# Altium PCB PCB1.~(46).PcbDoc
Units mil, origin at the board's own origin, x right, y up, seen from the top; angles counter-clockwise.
Board outline 6000 x 4000 mil, 2 copper layers (Top Layer, Bottom Layer); 37 components, 28 nets, 157 pads, 79 vias.
Unrouted connection lines stored in the file: 48.
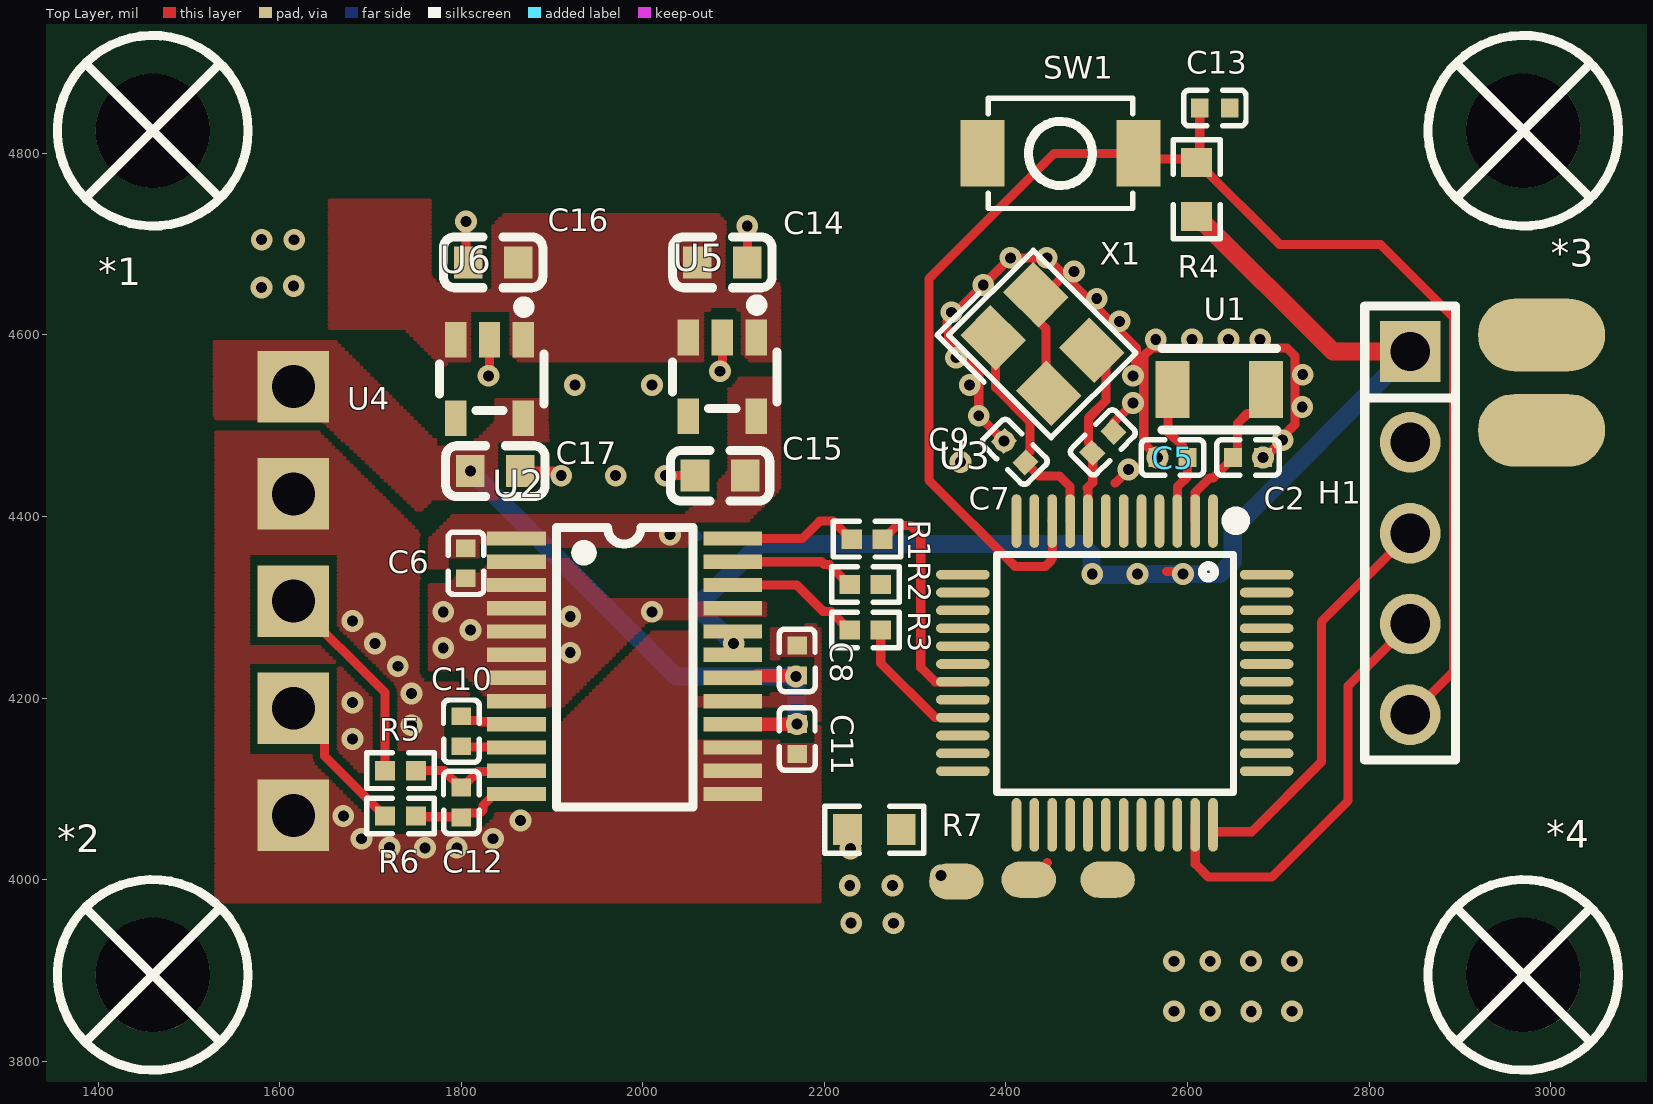
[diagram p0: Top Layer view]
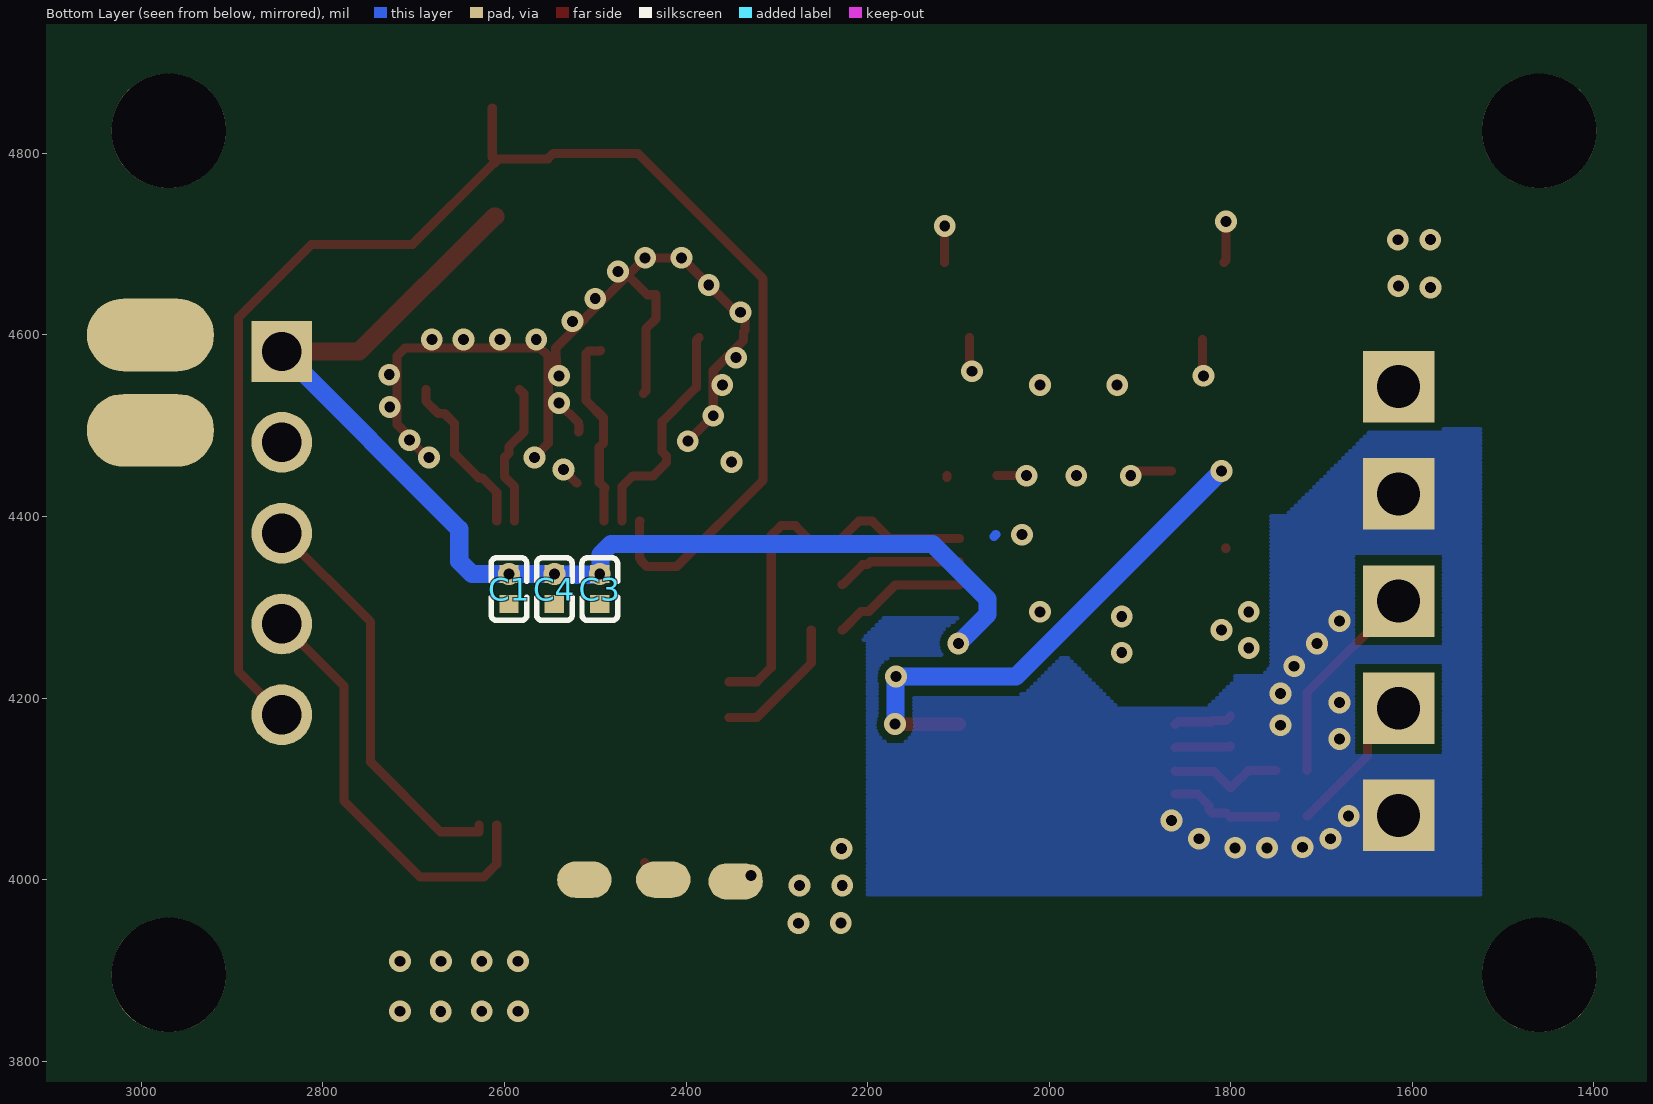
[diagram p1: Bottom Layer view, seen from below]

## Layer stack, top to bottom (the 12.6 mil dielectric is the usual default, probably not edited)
Top Solder: solder mask 0.4, Solder Resist, Dk 3.5
Top Layer: signal copper 1.4
Dielectric 1: dielectric 12.6, FR-4, Dk 4.8
Bottom Layer: signal copper 1.4
Bottom Solder: solder mask 0.4, Solder Resist, Dk 3.5

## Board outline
1000,1000 7000,1000 7000,5000 1000,5000

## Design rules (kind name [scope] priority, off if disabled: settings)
Clearance [All] p1: gap=8 ignorepadtopadclearanceinfootprint=FALSE
ComponentClearance [All] p1: gap=0 collisioncheckmode=3 verticalgap=0 showdistances=FALSE
HoleSize [All] p1: absolutevalues=TRUE maxlimit=130 minlimit=1 maxpercent=80.000 minpercent=20.000
MinimumSolderMaskSliver [All] p1: minsoldermaskwidth=4
PlaneConnect [All] p1: planeconnectstyle=Direct reliefexpansion=20 reliefentries=4 reliefconductorwidth=10 reliefairgap=10
PolygonConnect [All] p1: connectstyle=Direct reliefconductorwidth=10 reliefentries=4 polygonreliefangle="90 Angle" airgapwidth=10
RoutingVias [All] p1: holewidth=28 width=50 viastyle="Through Hole" minholewidth=28 minwidth=50 maxholewidth=28 maxwidth=50
SilkToSilkClearance [All] p1: silktosilkclearance=2
SilkToSolderMaskClearance [IsPad] p1: minsilkscreentomaskgap=2 clearancetoexposedcopper=TRUE
SolderMaskExpansion [All] p1: expansion=0 istentingtop=FALSE
SupplyNets "Schematic Supply Nets_2" [InNet('6V')] p1: voltage=0.000
SupplyNets "Schematic Supply Nets" [InNet('3V3')] p2: voltage=0.000
SupplyNets "Schematic Supply Nets_4" [InNet('5V')] p3: voltage=0.000
SupplyNets "Schematic Supply Nets_3" [InNet('DGND')] p4: voltage=0.000
SupplyNets "Schematic Supply Nets_1" [InNet('AGND')] p5: voltage=0.000
Width [All] p1: maxlimit=50 minlimit=10 preferedwidth=10
24 further rules are at their usual default settings.

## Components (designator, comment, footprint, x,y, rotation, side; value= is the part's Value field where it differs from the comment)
*1 "螺丝孔_1" M3螺丝 1460,4825 r0 top
*2 "螺丝孔_1" M3螺丝 1460,3895 r0 top
*3 "螺丝孔_1" M3螺丝 2970,4825 r0 top
*4 "螺丝孔_1" M3螺丝 2970,3895 r0 top
C1 "cc0402krx7r7bb104" C0402 2595,4320 r270 bottom value=100nF
C2 "cc0402jrnpo9bn220" C0402 2666.54,4465 r180 top value=22pF
C3 "cc0402krx7r7bb104" C0402 2495,4320 r270 bottom value=100nF
C4 "cc0402krx7r7bb104" C0402 2545,4320 r90 bottom value=100nF
C5 "cc0402jrnpo9bn220" C0402 2583.46,4465 r0 top value=22pF
C6 "cc0402krx7r7bb104" C0402 1805,4348.46 r270 top value=100nF
C7 "cc0402jrnpo9bn180" C0402 2506.7,4481.7 r45 top value=18pF
C8 "cc0402krx7r7bb104" C0402 2170,4241.54 r90 top value=100nF
C9 "cc0402jrnpo9bn180" C0402 2409.68,4471.29 r315 top value=18pF
C10 "cc0402krx7r7bb104" C0402 1800,4163.46 r90 top value=100nF
C11 "gcm155r71h103ka55d" C0402 2170,4155 r270 top value=10nF
C12 "gcm155r71h103ka55d" C0402 1800,4085 r270 top value=10nF
C13 "cc0402krx7r7bb104" C0402 2630,4850 r180 top value=100nF
C14 "cga0603x5r105k500jt" C0603 2087.56,4680 r0 top value=1uF
C15 "cga0603x5r105k500jt" C0603 2085,4445 r180 top value=1uF
C16 "cga0603x5r105k500jt" C0603 1835,4680 r180 top value=1uF
C17 "cga0603x5r105k500jt" C0603 1837.44,4450 r0 top value=1uF
H1 "pz254v-11-05p" HDR-TH_5P-P2.54-V-M 2845.25,4381.69 r270 top
R1 "frc0402f47r0ts" R0402 2247.04,4375 r0 top value=47Ω
R2 "frc0402f47r0ts" R0402 2245,4325 r0 top value=47Ω
R3 "frc0402f47r0ts" R0402 2245,4275 r0 top value=47Ω
R4 "frc0603f1002ts" R0603 2610.04,4760.31 r270 top value=10kΩ
R5 "frc0402f1000ts" R0402 1732.96,4120 r0 top value=100Ω
R6 "frc0402f1000ts" R0402 1732.96,4070 r0 top value=100Ω
R7 "0603waf0000t5e" R0603 2255,4055 r0 top value=0Ω
SW1 "ts-1088-ar02016" SW-SMD_L3.9-W3.0-P4.45 2460,4800 r0 top
U1 "fc31m2-32.768-ntlnndtl" CRYSTAL-SMD_L3.2-W1.5 2635,4540 r0 top value=32.768kHz
U2 "ads1232ipwr" TSSOP-24_L7.8-W4.4-P0.65-LS6.4-BL 1980,4235 r270 top
U3 "stm32g031c8t6" LQFP-48_L7.0-W7.0-P0.50-LS9.0-BL 2519.84,4227.68 r180 top
U4 "5个焊盘" 5个焊盘 1615,4543.1 r270 top
U5 "tps7a2033pdbvr" SOT-23-5_L2.9-W1.6-P0.95-LS2.8-BR 2087.56,4553.8 r90 top
U6 "tps7a2050pdbvr" SOT-23-5_L2.9-W1.6-P0.95-LS2.8-BR 1831.01,4551.56 r90 top
X1 "x32258mob4si" CRYSTAL-SMD_4P-L3.2-W2.5-BL 2440,4590 r315 top value=8MHz

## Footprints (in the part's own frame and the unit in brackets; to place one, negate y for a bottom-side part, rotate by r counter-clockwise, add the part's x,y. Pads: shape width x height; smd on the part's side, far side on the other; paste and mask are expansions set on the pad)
5个焊盘 [mm]
  rect 2x2 hole 1.2: 1(0,0) 2(3,0) 3(6.001,0) 4(9,0) 5(12,0)
C0402 [mm]
  rect 0.5x0.54 smd: 1(-0.42,0) 2(0.42,0)
  silkscreen extent -0.87,-0.5 0.87,0.5
C0603 [mm]
  rect 0.8x0.9 smd: 1(-0.7,0) 2(0.7,0)
  silkscreen extent -1.39,-0.71 1.39,0.71
CRYSTAL-SMD_4P-L3.2-W2.5-BL [mm]
  rect 1.4x1.2 smd: 1(-1.1,-0.85) 2(1.1,-0.85) 3(1.1,0.85) 4(-1.1,0.85)
  silkscreen extent -2.26,-1.91 2.03,1.68
CRYSTAL-SMD_L3.2-W1.5 [mm]
  rect 0.95x1.6 smd: 1(-1.308,0) 2(1.308,0)
  silkscreen extent -1.6,-1.14 1.6,1.14
HDR-TH_5P-P2.54-V-M [mm]
  rect 1.7x1.7 hole 1.1: 1(-5.08,0)
  round 1.7 hole 1.1: 2(-2.54,0) 3(0,0) 4(2.54,0) 5(5.08,0)
  silkscreen extent -6.35,-1.27 6.35,1.27
LQFP-48_L7.0-W7.0-P0.50-LS9.0-BL [mm]
  oval 0.27x1.5 smd paste+0 mask+0.05: 1(-2.75,-4.25) 2(-2.25,-4.25) 3(-1.75,-4.25) 4(-1.25,-4.25) 5(-0.75,-4.25) 6(-0.25,-4.25) 7(0.25,-4.25) 8(0.75,-4.25) 9(1.25,-4.25) 10(1.75,-4.25) 11(2.25,-4.25) 12(2.75,-4.25) 25(2.75,4.25) 26(2.25,4.25) 27(1.75,4.25) 28(1.25,4.25) 29(0.75,4.25) 30(0.25,4.25) 31(-0.25,4.25) 32(-0.75,4.25) 33(-1.25,4.25) 34(-1.75,4.25) 35(-2.25,4.25) 36(-2.75,4.25)
  oval 1.5x0.27 smd paste+0 mask+0.05: 13(4.25,-2.75) 14(4.25,-2.25) 15(4.25,-1.75) 16(4.25,-1.25) 17(4.25,-0.75) 18(4.25,-0.25) 19(4.25,0.25) 20(4.25,0.75) 21(4.25,1.25) 22(4.25,1.75) 23(4.25,2.25) 24(4.25,2.75) 37(-4.25,2.75) 38(-4.25,2.25) 39(-4.25,1.75) 40(-4.25,1.25) 41(-4.25,0.75) 42(-4.25,0.25) 43(-4.25,-0.25) 44(-4.25,-0.75) 45(-4.25,-1.25) 46(-4.25,-1.75) 47(-4.25,-2.25) 48(-4.25,-2.75)
  silkscreen extent -3.59,-4.46 3.3,3.34
M3螺丝 [mil]
  round 126 hole 126 paste-99999 mask+4: 1(0,0)
  silkscreen extent -105,-105 105,105
R0402 [mm]
  rect 0.566x0.54 smd paste-100 mask+0.051: 1(-0.433,0) 2(0.433,0)
  silkscreen extent -0.94,-0.5 0.94,0.5
R0603 [mil]
  rect 31.75x34.02 smd paste-3937.01 mask+2: 1(-29.66,0) 2(29.66,0)
  silkscreen extent -55,-26 55,26
SOT-23-5_L2.9-W1.6-P0.95-LS2.8-BR [mm]
  rect 1x0.6 smd paste+0 mask+0.05: 1(1.1,-0.95) 2(1.1,0) 3(1.1,0.95) 4(-1.1,0.95) 5(-1.1,-0.95)
  silkscreen extent -0.89,-1.52 2.16,1.4
SW-SMD_L3.9-W3.0-P4.45 [mm]
  rect 1.23x1.86 smd: 1(-2.185,0) 2(2.185,0)
  silkscreen extent -2.03,-1.54 2.03,1.54
TSSOP-24_L7.8-W4.4-P0.65-LS6.4-BL [mm]
  rect 0.4x1.65 smd: 1(-3.575,-3.023) 2(-2.925,-3.023) 3(-2.275,-3.023) 4(-1.625,-3.023) 5(-0.975,-3.023) 6(-0.325,-3.023) 7(0.325,-3.023) 8(0.975,-3.023) 9(1.625,-3.023) 10(2.275,-3.023) 11(2.925,-3.023) 12(3.575,-3.023) 13(3.575,3.023) 14(2.925,3.023) 15(2.275,3.023) 16(1.625,3.023) 17(0.975,3.023) 18(0.325,3.023) 19(-0.325,3.023) 20(-0.975,3.023) 21(-1.625,3.023) 22(-2.275,3.023) 23(-2.925,3.023) 24(-3.575,3.023)
  silkscreen extent -3.89,-1.91 3.94,1.9

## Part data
C1 C3 C4 C6 C8 C10 C13: "容值:100nF;精度:±10%;额定电压:16V;温度系数:X7R;", JLCPCB Part Class="Extended Part", LCSC Part Name="100nF ±10% 16V", Manufacturer=YAGEO(国巨), ManufacturerPart=CC0402KRX7R7BB104, Temperature Coefficient=X7R, Tolerance=±10%, Voltage Rating=16V
C2 C5: "容值:22pF;精度:±5%;额定电压:50V;温度系数:NP0;", JLCPCB Part Class="Extended Part", LCSC Part Name="22pF ±5% 50V", Manufacturer=YAGEO(国巨), ManufacturerPart=CC0402JRNPO9BN220, Temperature Coefficient=NP0, Tolerance=±5%, Voltage Rating=50V
C7 C9: "容值:18pF;精度:±5%;额定电压:50V;温度系数:NP0;", JLCPCB Part Class="Extended Part", LCSC Part Name="18pF ±5% 50V", Manufacturer=YAGEO(国巨), ManufacturerPart=CC0402JRNPO9BN180, Temperature Coefficient=NP0, Tolerance=±5%, Voltage Rating=50V
C11 C12: "容值:10nF;精度:±10%;额定电压:50V;温度系数:X7R;", JLCPCB Part Class="Extended Part", LCSC Part Name="10nF ±10% 50V", Manufacturer=muRata(村田), ManufacturerPart=GCM155R71H103KA55D, Temperature Coefficient=X7R, Tolerance=±10%, Voltage Rating=50V
C14 C15 C16 C17: "容值:1uF;精度:±10%;额定电压:50V;温度系数:X5R;", JLCPCB Part Class="Extended Part", LCSC Part Name="1uF ±10% 50V 停产", Manufacturer=HRE(芯声), ManufacturerPart=CGA0603X5R105K500JT, Temperature Coefficient=X5R, Tolerance=±10%, Voltage Rating=50V
H1: "插针结构:1x5P;间距:2.54mm;行距:-;圆针/方针:方针;安装方式:直插;排数:单排;总PIN位数:5P;额定电流:3A;额定电压:250V;配合针长度:6mm;塑高:2.5mm;端接针长度:3mm;触头材质:黄铜;触头镀层:-;工作温度:-40℃~+105℃;颜色:黑色;", Color=黑色, Current Rating=3A, JLCPCB Part Class="Extended Part", LCSC Part Name="1x5P 间距:2.54mm 方针 直插", Manufacturer=XFCN(兴飞), ManufacturerPart=PZ254V-11-05P, Operating Temperature=-40℃~+105℃, Voltage Rating (Max)=250V
R1 R2 R3: "电阻类型:厚膜电阻;阻值:47Ω;精度:±1%;功率:62.5mW;工作电压:50V;温度系数:±100ppm/℃;", JLCPCB Part Class="Extended Part", LCSC Part Name="47Ω ±1% 62.5mW 厚膜电阻", Manufacturer=FOJAN(富捷), ManufacturerPart=FRC0402F47R0TS, Operating Temperature=-55℃~+155℃, Power(Watts)=62.5mW, Temperature Coefficient=±100ppm/℃, Tolerance=±1%, Voltage-Supply(Max)=50V
R4: "电阻类型:厚膜电阻;阻值:10kΩ;精度:±1%;功率:100mW;工作电压:75V;温度系数:±100ppm/℃;", JLCPCB Part Class="Extended Part", LCSC Part Name="10kΩ ±1% 100mW 厚膜电阻", Manufacturer=FOJAN(富捷), ManufacturerPart=FRC0603F1002TS, Operating Temperature=-55℃~+155℃, Power(Watts)=100mW, Temperature Coefficient=±100ppm/℃, Tolerance=±1%, Voltage-Supply(Max)=75V
R5 R6: "电阻类型:厚膜电阻;阻值:100Ω;精度:±1%;功率:62.5mW;工作电压:50V;温度系数:±100ppm/℃;", JLCPCB Part Class="Extended Part", LCSC Part Name="100Ω ±1% 62.5mW 厚膜电阻", Manufacturer=FOJAN(富捷), ManufacturerPart=FRC0402F1000TS, Operating Temperature=-55℃~+155℃, Power(Watts)=62.5mW, Temperature Coefficient=±100ppm/℃, Tolerance=±1%, Voltage-Supply(Max)=50V
R7: "电阻类型:厚膜电阻;阻值:0Ω;精度:±1%;功率:100mW;工作电压:75V;温度系数:-;", JLCPCB Part Class="Basic Part", LCSC Part Name="0Ω ±1% 100mW 厚膜电阻", Manufacturer=UNI-ROYAL(厚声), ManufacturerPart=0603WAF0000T5E, Operating Temperature=-55℃~+155℃, Power(Watts)=100mW, Temperature Coefficient=-, Tolerance=±1%, Voltage-Supply(Max)=75V
SW1: "电路结构:单刀单掷;按钮形状:圆形按钮;作用力:1.6N;安装方式:立贴;开关长度:3.9mm;开关宽度:3mm;开关高度:2mm;带支架:不带支架;触点电流:50mA;额定电压:12V;带灯:-;工作寿命:10万次;", Actuator/Cap Color=黑色, Contact Current=50mA, IP Rating=-, JLCPCB Part Class="Basic Part", LCSC Part Name="3.9*3*2mm 立贴 轻触开关", Manufacturer=XUNPU(讯普), ManufacturerPart=TS-1088-AR02016, Operating Force=1.6N, Operating Temperature=-30℃~+80℃, Voltage Rating=12V
U1: "晶振类型:贴片晶振;频率:32.768kHz;常温频差:±10ppm;负载电容:12.5pF;频率稳定度:±10ppm;", Equivalent Series Resistance(ESR)=70kΩ, Frequency Stability=±10ppm, JLCPCB Part Class="Extended Part", LCSC Part Name="3215 2P 32.768kHz 12.5pF ±10ppm -40~+85℃(±10ppm)", Load Capacitance=12.5pF, Manufacturer=HCI(杭晶), ManufacturerPart=FC31M2-32.768-NTLNNDTL, Operating Temperature=-40℃~+85℃
U2: "分辨率(位):24;采样率:10Hz;工作电压:2.7V~5.3V;接口类型:SPI;", Clock Frequency=4.9152MHz；200kHz~8MHz, JLCPCB Part Class="Extended Part", LCSC Part Name="用于桥式传感器的24bit 模数转换器", Manufacturer=TI(德州仪器), ManufacturerPart=ADS1232IPWR, Operating Temperature=-40℃~+105℃, Quiescent Current (Iq)=1.3uA, Temperature Sensors=内置, Voltage - Supply=2.7V~5.3V, Voltage Reference=外置, Voltage Reference Drift=-
U3: "CPU内核:ARM Cortex-M0+;CPU最大主频:64MHz;CPU位数:32 Bit;", JLCPCB Part Class="Extended Part", LCSC Part Name="主流Arm Cortex-M0+ MCU，具有64 KB Flash存储器、8 KB RAM、64 MHz CPU、2x USART、定时器、ADC和通信接口，1.7-3.6V", Manufacturer=ST(意法半导体), ManufacturerPart=STM32G031C8T6, Operating Temperature=-40℃~+85℃, Voltage - Supply=1.7V~3.6V
U5: "输出类型:固定;最大输入电压:6V;输出电压:3.3V;输出电流:300mA;输出极性:正极;", Dropout Voltage=140mV@(300mA), JLCPCB Part Class="Extended Part", LCSC Part Name="具有高 PSRR 的 300mA、超低噪声、低 IQ、低压降 (LDO) 线性稳压器", Manufacturer=TI(德州仪器), ManufacturerPart=TPS7A2033PDBVR, Maximum Input Voltage=6V, Operating Temperature=-40℃~+125℃@(Tj), Output Current=300mA, Output Voltage=3.3V, standby current=15uA
U6: "输出极性:正极;工作电压:6V;输出电压:5V;输出电流:300mA;电源纹波抑制比(PSRR):65dB@(100Hz);输出类型:固定;", JLCPCB Part Class="Extended Part", LCSC Part Name="800mV~5.5V 300mA 6V", Manufacturer=TI(德州仪器), ManufacturerPart=TPS7A2050PDBVR, Operating Temperature=-40℃~+125℃@(Tj), Output Current=300mA, Output Voltage=5V, Power Supply Rejection Ratio (PSRR)=65dB@(100Hz), standby current=6.5uA, Voltage - Supply=6V, Voltage Dropout=140mV@(300mA)
X1: "晶振类型:贴片晶振;频率:8MHz;常温频差:±10ppm;负载电容:12pF;频率稳定度:±20ppm;", Equivalent Series Resistance(ESR)=180Ω, Frequency Stability=±20ppm, JLCPCB Part Class="Extended Part", LCSC Part Name="YSX321SL 8MHZ 4P 3225 12PF ±10PPM -40~85℃ (±20PPM)", Load Capacitance=12pF, Manufacturer=YXC(扬兴晶振), ManufacturerPart=X32258MOB4SI, Normal temperature Frequency Tolerance=±10ppm, Operating Temperature=-40℃~+85℃

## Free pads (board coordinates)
  oval 60x40 all layers, no hole: 7(2345.3,3998) 7(2425,4000) 7(2512,3999.83)
  oval 140x80 all layers, no hole: 7(2990,4495) 7(2990,4600)

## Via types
v1: diameter 24, hole 12, Top Layer to Bottom Layer, tented both sides, 79 vias

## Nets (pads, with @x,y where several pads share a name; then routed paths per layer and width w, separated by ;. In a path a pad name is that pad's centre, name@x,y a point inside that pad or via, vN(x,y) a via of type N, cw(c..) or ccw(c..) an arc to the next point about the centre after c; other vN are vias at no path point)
3V3: C1.1 C3.1 C4.2 C6.1 C15.1 H1.1 R4.2 U2.1 U2.19 U2.20 U3.4 U3.5 U3.6 U5.5 | length 1338.4
  Top Layer w10: C6.1 C6.1@1805.79,4365 ; C15.1@2112.56,4443.03 C15.1 ; v1(2495,4336.54) v1@2497.68,4339.22 ; 2576.89,4339.22 2592.32,4339.22 v1(2595,4336.54)
  Top Layer w20: R4.2 2611.17,4730.65 2760.13,4581.69 H1.1
  Bottom Layer w10: v1@2028.6,4378.6 v1(2030,4380) ; 2058.74,4380 2060.53,4378.21
  Bottom Layer w20: v1(2100,4260) 2067.7,4292.3 2067.7,4308.87 2128.71,4369.89 2482.65,4369.89 2494.37,4358.17 2494.37,4336.7 2494.53,4336.54 v1(2495,4336.54) ; C3.1@2495.69,4335.85 C4.2@2544.31,4335.85 ; C4.2@2545.63,4336.49 C1.1@2594.37,4336.49 ; v1(2595,4336.54) 2635.63,4336.54 2649.85,4350.76 2649.85,4386.29 H1.1
  other v1: 2545,4336.54
5V: C8.1 C11.1 C17.1 U2.16 U2.18 U4.1 U6.5 | length 649.2
  Top Layer w10: v1(2168.61,4223.6) C8.1 ; v1(2169.74,4171.28) C11.1
  Top Layer w15: U2.16 2099.26,4171.28 v1(2169.74,4171.28) ; U2.18 2123.61,4222.21 2125.81,4224.42 2167.79,4224.42 v1(2168.61,4223.6)
  Bottom Layer w10: v1(2168.61,4223.6) v1@2169.17,4223.04 ; v1@2169.17,4171.85 v1(2169.74,4171.28)
  Bottom Layer w20: v1(1810,4450) 2036.39,4223.6 v1(2168.61,4223.6) ; v1@2169.17,4171.85 v1@2169.17,4223.04
6V: C14.1 C16.1 pad.7@2990,4600 U5.1 U5.3 U6.1 U6.3
AGND: C8.2 C11.2 R7.1 U2.13 U2.14 U2.15 U2.17 U4.2 U4.5
  other v1: 1760,4035 1795,4035 1720.87,4035.63 1690,4045 1835,4045 1865,4065 1670,4070 1680,4155 1745,4170 1680,4195 1745,4205 1730,4235 1705,4260 1680,4285
AINN1: R6.1 U4.4 | length 160.9
  Top Layer w10: U4.4 1649.37,4154.39 1649.37,4136.04 1715.41,4070 R6.1
AINP1: R5.1 U4.3 | length 228.7
  Top Layer w10: U4.3 1715.92,4205.94 R5.1
DGND: C1.2 C2.1 C3.2 C4.1 C5.1 C6.2 C7.2 C9.1 C13.1 C14.2 C15.2 C16.2 C17.2 H1.2 pad.7@2345.3,3998 pad.7@2990,4495 R7.2 SW1.1 U2.2 U2.3 U2.4 U2.5 U2.6 U2.7 U2.8 U2.21 U3.7 U5.2 U6.2 X1.2 X1.4 | length 1352.5
  Top Layer w10: v1(1805,4725) 1805,4682.44 C16.2 ; v1(1830,4555) 1831.02,4556.02 U6.2 ; C17.2 1901.21,4450 1906.21,4445 v1(1910,4445) ; v1(2025,4445) C15.2 ; v1(2085,4560) 2087.57,4562.56 U5.2 ; v1(2115,4720) 2115.12,4719.88 C14.2 ; v1(2397.98,4482.98) v1(2370,4510.96) 2370,4560.88 2336.52,4594.36 2336.52,4603.48 2335,4605 2335,4615 v1(2405,4685) v1(2445,4685) v1@2464.14,4665.86 ; X1.2 2444.18,4538.5 2444.18,4606.81 2433.04,4617.95 X1.4 2442.57,4644.29 v1@2464.14,4665.86 ; C7.2 2517.83,4493.95 2517.83,4500.8 2518.39,4501.35 2518.39,4503.39 v1(2540,4525) ; v1(2540,4555) 2542.68,4557.68 2542.68,4574.07 2543.48,4574.87 2543.48,4585.64 2512.06,4617.06 2512.06,4617.94 v1@2464.14,4665.86 ; v1(2566.92,4465) 2566.92,4465.79 2551.8,4480.91 2551.8,4576.88 2560.36,4585.44 2709.64,4585.44 2718.2,4576.88 v1@2718.2,4556.26 ; v1(2683.08,4465) 2687.92,4469.84 C2.1@2687.92,4470.63 ; C2.1@2683.08,4465.79 C2.1@2687.92,4470.63 ; v1(2726.38,4520.61) v1@2718.2,4520.61 ; v1(2726.94,4556.26) v1@2718.2,4556.26 ; C2.1@2687.92,4470.63 2691.22,4470.63 v1(2704.71,4484.12) 2704.71,4487.91 2718.2,4501.4 v1@2718.2,4520.61 ; v1@2718.2,4520.61 v1@2718.2,4556.26
  other v1: 2585,3855 2625,3855 2670.24,3854.54 2715,3855 2585,3910 2625,3910 2670,3910 2715,3910 2229.44,3952.22 2276.16,3951.9 2227.87,3993.61 2274.91,3993.61 2328.34,4004.38 2228.81,4034.06 1920,4250 1780,4255 1810,4275 1920,4290 1780,4295 2010,4295 1970,4445 2350,4460 1925,4545 2010,4545 2360,4545 2345,4575 2565,4595 2605,4595 2645,4595 2680,4595 2525,4615 2340,4625 2500,4640 1579.72,4652.35 1615.25,4654.08 2375,4655 2475,4670 1580,4705 1615.83,4704.92
DOUT: R1.2 U3.19 | length 251.1
  Top Layer w10: R1.2 2264.59,4375 2279.58,4390 2295.22,4390 2306.09,4379.12 2306.09,4233.84 2321.97,4217.96 2352.4,4217.96 U3.19
NetC2_2: C2.2 U1.2 U3.2 | length 183.5
  Top Layer w10: U3.2 2608.54,4395.12 2608.54,4426.49 2624.61,4442.56 2628.35,4442.56 2654.84,4469.06 2654.84,4502.3 2666.05,4513.5 2672.8,4513.5 2686.5,4527.21 U1.2
NetC5_2: C5.2 U1.1 U3.3 | length 160.6
  Top Layer w10: U1.1 2578.5,4535 2578.5,4493.5 2595.16,4476.85 2595.16,4469.84 C5.2 2600,4443.85 2588.86,4432.71 2588.86,4395.12 U3.3
NetC7_1: C7.1 U3.8 X1.3 | length 214.9
  Top Layer w10: U3.8 U3.8 2490.35,4402.44 2490.35,4429.95 2489.11,4431.19 2495.56,4437.63 2495.56,4476.29 2490.91,4480.93 2490.91,4508.56 2510.11,4527.75 2510.11,4579.54 2507.33,4582.33 2495,4582.33 X1.3
NetC9_2: C9.2 U3.9 X1.1 | length 254.5
  Top Layer w10: X1.1 2388.5,4594.18 2388.5,4542.39 2426.34,4504.54 2426.34,4471.41 2421.37,4466.44 C9.2 2436.12,4444.85 2458.69,4444.85 2470.67,4432.86 2470.67,4402.44 2470.67,4395.04 U3.9
NetC10_1: C10.1 U2.10 | length 61.6
  Top Layer w10: C10.1 1800.74,4146.18 1860.25,4146.18 U2.10
NetC10_2: C10.2 U2.9 | length 64.7
  Top Layer w10: C10.2 1804.84,4175.16 1819.84,4175.16 1821.11,4173.89 1858.13,4173.89 U2.9
NetC12_1: C12.1 R5.2 U2.11 | length 126.2
  Top Layer w10: R5.2 1780.75,4120 1799.21,4101.54 C12.1 1800.79,4101.54 1818.52,4119.27 1860.43,4119.27 U2.11
NetC12_2: C12.2 R6.2 U2.12 | length 125.3
  Top Layer w10: R6.2 1750.77,4069.23 1799.23,4069.23 C12.2 1804.84,4073.3 1820.44,4073.3 1823.63,4076.5 1823.63,4081.5 1836.39,4094.26 U2.12
NetR1_1: R1.1 U2.24 | length 147.3
  Top Layer w10: U2.24 2175.54,4375.74 2194.8,4395 2209.49,4395 2229.49,4375 R1.1
NetR2_1: R2.1 U2.23 | length 139.4
  Top Layer w10: U2.23 2196.82,4350.15 2199.94,4347.03 2205.42,4347.03 2227.45,4325 R2.1
NetR3_1: R3.1 U2.22 | length 149.5
  Top Layer w10: U2.22 2169.37,4324.56 2198.42,4295.51 2206.94,4295.51 2227.45,4275 R3.1
NRST: C13.2 H1.5 R4.1 SW1.2 U3.10 | length 1671.2
  Top Layer w10: U3.10 2451.06,4394.88 2451.06,4354.31 2451.1,4354.27 2449.62,4352.79 2449.62,4351.29 2443.25,4344.91 2410.11,4344.91 2315,4440.02 2315,4661.81 2453.19,4800 SW1.2 2552.11,4793.91 R4.1@2611.38,4793.91 ; R4.1 2610.25,4789.76 R4.1@2611.38,4789.76 ; C13.2 2613.46,4795.99 R4.1@2611.38,4793.91 ; H1.5 2893.09,4229.53 2893.09,4619.16 2812.43,4699.82 2701.33,4699.82 R4.1@2611.38,4789.76 ; R4.1@2611.38,4789.76 R4.1@2611.38,4793.91
PDWN: R3.2 U3.21 | length 151.8
  Top Layer w10: R3.2 2262.04,4238.52 2321.97,4178.59 2352.4,4178.59 U3.21
SCLK: R2.2 U3.20
SWCLK: H1.3 U3.36 | length 451.4
  Top Layer w10: U3.36 2628.11,4052.84 2628.27,4052.68 2670.54,4052.68 2747.4,4129.53 2747.4,4283.84 H1.3
SWDIO: H1.4 U3.35 | length 475.3
  Top Layer w10: U3.35 2608.54,4060.24 2608.54,4017.32 2623.09,4002.77 2692.63,4002.77 2776.9,4087.04 2776.9,4213.35 H1.4
USART1_RX: pad.7@2512,3999.83 U3.32
USART1_TX: pad.7@2425,4000 U3.29
USART2_RX: U3.14
USART2_TX: U3.13
pads on no net: *1.1 *2.1 *3.1 *4.1 U3.1 U3.11 U3.12 U3.15 U3.16 U3.17 U3.18 U3.22 U3.23 U3.24 U3.25 U3.26 U3.27 U3.28 U3.30 U3.31 U3.33 U3.34 U3.37 U3.38 U3.39 U3.40 U3.41 U3.42 U3.43 U3.44 U3.45 U3.46 U3.47 U3.48 U5.4 U6.4
copper on no net: | length 62.9
  Top Layer w10: 2425,4000 2426.88,4000 2445.47,4018.59 ; 2504.65,4007.18 2512,3999.83 ; 2520.16,4436.85 v1(2535,4451.69) v1@2535,4455

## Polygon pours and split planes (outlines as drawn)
DGND on Top Layer "NONET_L-01_P-001" (hatched Horizontal grid 4 track 5, remove dead copper, pour order 15): 1389.4,3473.32 1389.4,2330.12 3114.4,2330.12 3114.4,3466.93
5V on Top Layer "NONET_L-01_P-001" (hatched Horizontal grid 4 track 5, remove dead copper, pour order 9): 1893.57,4530 1873.57,4530 1838.57,4530 1838.57,4505 1818.57,4485 1768.57,4485 1658.57,4595 1528.57,4595 1528.57,4505 1645,4505 1680,4475 1753.57,4405 1768.57,4420 1838.57,4420 1838.57,4480 1843.57,4485 1848.57,4480 1895,4480
AGND on Top Layer "NONET_L-01_P-001" (hatched Horizontal grid 4 track 5, remove dead copper, pour order 7): 1565,4495 1640,4495 1755,4380 1755,4225 1795,4225 1827.5,4192.5 1907.5,4192.5 1915,4185 2010,4280 2180,4280 2185,4285 2195,4275 2195,3975 2180,3975 2160,3975 1530,3975 1530,4495
DGND on Top Layer "NONET_L-01_P-001" (hatched Horizontal grid 4 track 5, remove dead copper, pour order 5): 1765,4340 1820,4340 1832.5,4352.5 1830,4355 1830,4365 1905,4365 1960,4310 2135,4310 2135,4290 2130,4285 2005,4285 1905,4185 1830,4185 1830,4200 1800,4230 1765,4230
6V on Top Layer "NONET_L-01_P-001" (hatched Horizontal grid 4 track 5, remove dead copper, pour order 3): 1655,4750 1655,4605 1740,4605 1780,4565 1785,4570 1810,4570 1810,4615 1820,4625 1855,4625 1855,4580 1865,4570 2070,4570 2070,4625 2075,4630 2105,4630 2105,4585 2120,4570 2150,4570 2150,4655 2140,4665 2090,4665 2090,4725 2080,4735 1850,4735 1835,4720 1835,4650 1780,4650 1765,4665 1765,4750
3V3 on Top Layer "NONET_L-01_P-001" (hatched Horizontal grid 4 track 5, remove dead copper, pour order 2): 2095,4555 2095,4450 2045,4400 1790,4400 1765,4375 1765,4340 1820,4340 1845,4365 2045,4365 2070,4390 2110,4390 2150,4430 2150,4545 2140,4555
DGND on Bottom Layer "NONET_L-01_P-001" (hatched Horizontal grid 4 track 5, remove dead copper, pour order 16): 3114.4,3473.32 3114.4,2325.12 1389.4,2325.12 1389.4,3466.93
AGND on Bottom Layer "NONET_L-01_P-001" (hatched Horizontal grid 4 track 5, remove dead copper, pour order 12): 1525,4500 1640,4500 1740,4400 1755,4400 1755,4235 1765,4225 1795,4225 1795,4220 1825,4190 1925,4190 2025,4290 2180,4290 2205,4265 2200,4260 2200,3980 1525,3980

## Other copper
Top Layer:
  pour cut-out: 2330,4625 2405,4700 2405,4705 2445,4705 2540,4610 2540,4605 2550,4595 2565,4610 2685.08,4610 2720,4575.08 2720,4480 2685,4445 2545,4445 2500,4490 2470,4460 2390,4460 2350,4500 2355,4505 2355,4550 2320,4585 2325,4590 2325,4630

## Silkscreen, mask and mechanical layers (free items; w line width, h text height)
Mechanical 1:
  lines w10: 1345,3775 3085,3775 3085,4930 1345,4930 1345,3775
